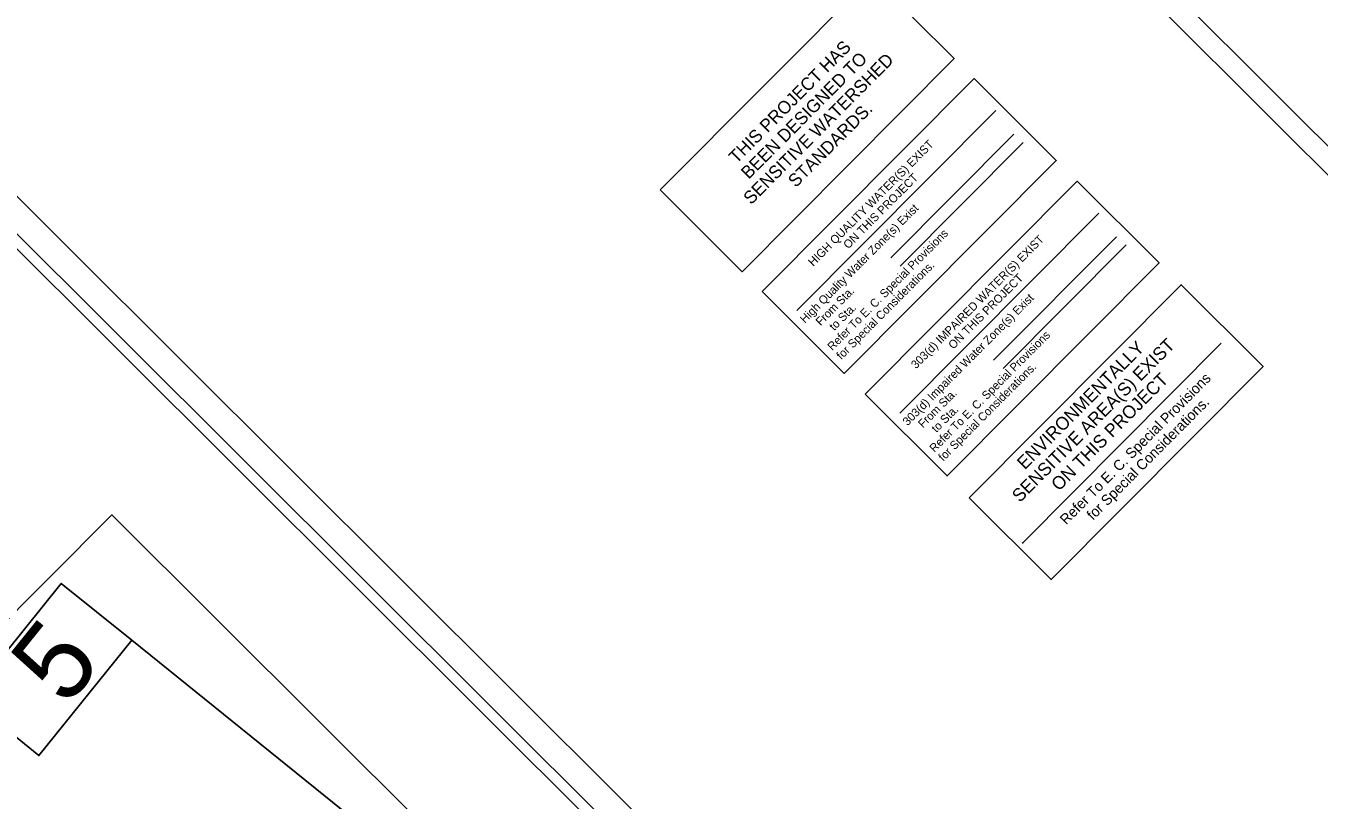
# Model space of a CAD drawing. Extents: x 1484932 to 1495672, y 495497 to 506262.
# Drawn here: x 1488841 to 1491317, y 499926 to 501407 of the extents above; entities that cross this region are included whole.
import ezdxf

# ---------------------------------------------------------------- set-up
doc = ezdxf.new("R2010")
doc.units = 0
for name, color, linetype in [('Old_Level_18', 7, 'Continuous'), ('Prop DSN Text', 7, 'Continuous'), ('Prop DSN White Annotation Label', 7, 'Continuous'), ('Scratch_Level_4', 7, 'Continuous'), ('Sheet Plot Border Inside CELL', 7, 'Continuous'), ('Sheet Plot Border Outside CELL', 7, 'Continuous')]:
    doc.layers.add(name, color=color, linetype=linetype)

msp = doc.modelspace()

# ---------------------------------------------------------------- linework, layer by layer
at = {"layer": 'Old_Level_18'}
for p, q in [((1490710.4, 499129.2), (1488558.1, 501272.7)), ((1488543.4, 501258.8), (1490253, 499556.3))]:
    msp.add_line(p, q, dxfattribs=at)
at = {"layer": 'Prop DSN White Annotation Label'}
for points in [[(1489043.4, 500231.5), (1488865.6, 500011), (1488730.5, 500119.9), (1488908.3, 500340.4)], [(1488865.6, 500011), (1488730.5, 500119.9), (1488058.3, 499286.4), (1488849.5, 498594.9), (1489725.7, 499681.3), (1489043.4, 500231.5)]]:
    msp.add_lwpolyline(points, close=True, dxfattribs=at)
at = {"layer": 'Scratch_Level_4'}
for p, q in [((1490496.5, 500963.3), (1490732, 501199.8)), ((1490514.5, 500947.5), (1490750.1, 501183.9)), ((1490693.4, 500767.1), (1490929, 501003.6)), ((1490711.5, 500751.3), (1490947, 500987.8))]:
    msp.add_line(p, q, dxfattribs=at)
for points in [[(1490054.9, 501093.1), (1490460.7, 501500.6), (1490617.8, 501344.2), (1490212, 500936.7)], [(1490250.4, 500898.5), (1490656.2, 501306), (1490813.2, 501149.6), (1490407.4, 500742.1)], [(1490447.3, 500702.3), (1490853.2, 501109.8), (1491010.2, 500953.4), (1490604.4, 500545.9)], [(1490646.4, 500504), (1491052.2, 500911.6), (1491209.3, 500755.1), (1490803.5, 500347.6)], [(1486969.7, 498427.7), (1489005, 500471.4), (1490008.1, 499472.4), (1487972.8, 497428.7)]]:
    msp.add_lwpolyline(points, close=True, dxfattribs=at)
for points in [[(1490316.7, 500862.2), (1490317.5, 500863), (1490697.6, 501244.7)], [(1490513.7, 500666.1), (1490514.4, 500666.8), (1490894.6, 501048.6)], [(1490748.4, 500417.4), (1490749.1, 500418.1), (1491129.4, 500799.9)]]:
    msp.add_lwpolyline(points, dxfattribs=at)
at = {"layer": 'Sheet Plot Border Inside CELL'}
msp.add_lwpolyline([(1492087.5, 500426.4), (1495619.8, 503973.4), (1493373.6, 506210.2), (1489841.3, 502663.3)], close=True, dxfattribs=at)
at = {"layer": 'Sheet Plot Border Outside CELL'}
for points in [[(1492102.5, 500356.3), (1495671.9, 503940.6), (1493340.6, 506262.2), (1489771.2, 502678)], [(1488496.6, 501405.6), (1484931.7, 497825.9), (1487270, 495497.3), (1490834.9, 499077)]]:
    msp.add_lwpolyline(points, close=True, dxfattribs=at)

# ---------------------------------------------------------------- texts
at = {"layer": 'Prop DSN Text'}
msp.add_text('5', height=150, rotation=51.1156, dxfattribs=at).set_placement((1488918.6, 500101.9))
at = {"layer": 'Scratch_Level_4'}
for s, height, p in [('THIS PROJECT HAS', 24.498, (1490201.3, 501142.1)), ('BEEN DESIGNED TO ', 24.498, (1490224.6, 501112.3)), ('SENSITIVE WATERSHED', 24.498, (1490229.1, 501063.6)), ('STANDARDS.', 24.5, (1490314.7, 501096.4)), ('    HIGH QUALITY WATER(S) EXIST', 15.923, (1490331.2, 500929.1)), ('                ON THIS PROJECT', 15.923, (1490348.3, 500912.1)), ('High Quality Water Zone(s) Exist', 15.923, (1490332.2, 500836.9)), ('Refer To E. C. Special Provisions', 15.923, (1490384.7, 500784.6)), ('    303(d) IMPAIRED WATER(S) EXIST', 15.923, (1490528.2, 500733)), ('for Special Considerations.', 15.923, (1490402, 500767.3)), ('                 ON THIS PROJECT', 15.923, (1490545.2, 500716)), ('   From Sta.                      ', 15.923, (1490349.6, 500819.6)), ('303(d) Impaired Water Zone(s) Exist', 15.923, (1490528.8, 500641)), ('     to Sta.', 15.923, (1490367.3, 500801.9)), ('Refer To E. C. Special Provisions', 15.923, (1490580.1, 500590)), ('SENSITIVE AREA(S) EXIST', 24.879, (1490743.7, 500493.9)), ('ENVIRONMENTALLY ', 24.879, (1490753.2, 500556.7)), ('for Special Considerations.', 15.923, (1490597.1, 500573)), ('ON THIS PROJECT', 24.879, (1490818.6, 500515.7)), ('Refer To E. C. Special Provisions', 19.903, (1490832.4, 500451.2)), ('   From Sta.                      ', 15.923, (1490545.9, 500624)), ('for Special Considerations.', 19.903, (1490883.7, 500460)), ('     to Sta.', 15.923, (1490563, 500607))]:
    msp.add_text(s, height=height, rotation=45.1186, dxfattribs=at).set_placement(p)

doc.saveas('drawing.dxf')
